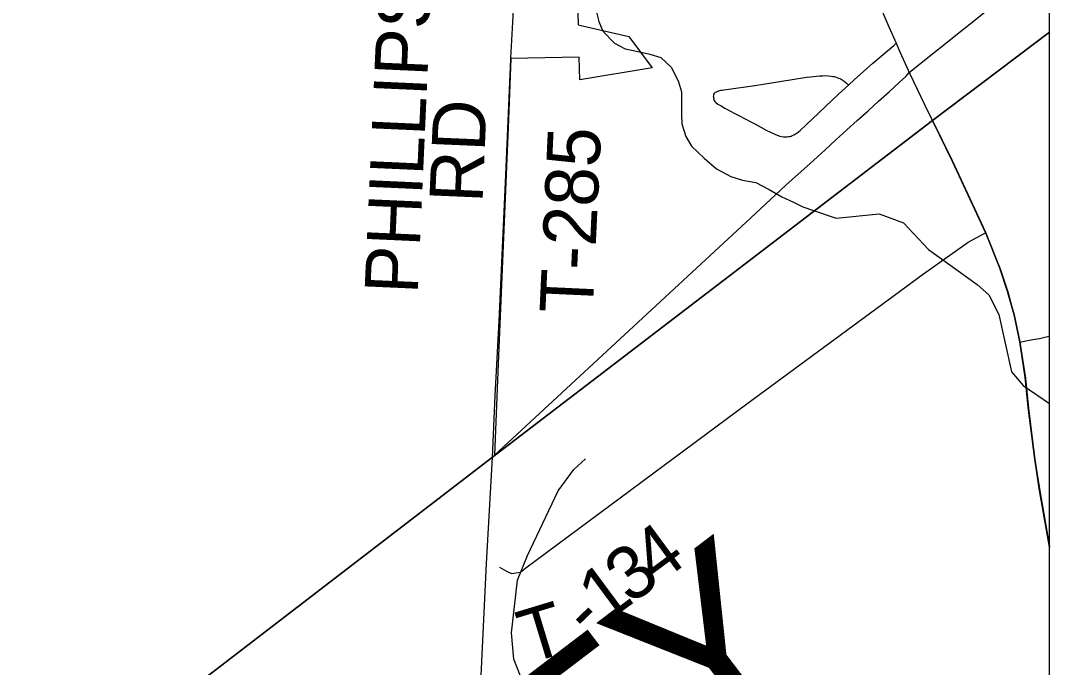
# Model space of a CAD drawing. Extents: x 0 to 1052, y -194 to 246.
# Drawn here: x 7.683 to 8.782, y 19.757 to 20.448 of the extents above; entities that cross this region are included whole.
import ezdxf

# ---------------------------------------------------------------- set-up
doc = ezdxf.new("R2010")
doc.units = 0
for name, color, linetype in [('GM_X_City_Street', 7, 'Continuous'), ('GM_X_Corporation', 7, 'Continuous'), ('GM_X_County_Road', 7, 'Continuous'), ('GM_X_County_Text', 7, 'Continuous'), ('GM_X_Major_River', 7, 'Continuous'), ('GM_X_Minor_River', 7, 'Continuous'), ('GM_X_State_Route', 7, 'Continuous'), ('GM_X_Township_Road', 7, 'Continuous'), ('GM_X_Township_Road_Text', 7, 'Continuous')]:
    doc.layers.add(name, color=color, linetype=linetype)

msp = doc.modelspace()

# ---------------------------------------------------------------- linework, layer by layer
at = {"layer": 'GM_X_City_Street'}
for points in [[(8.4233, 20.3666), (8.4232, 20.3657), (8.4233, 20.3649), (8.4235, 20.364), (8.4238, 20.3629), (8.4241, 20.3623), (8.4248, 20.3613), (8.4259, 20.3601), (8.4281, 20.3584), (8.4315, 20.3564), (8.4356, 20.354), (8.4462, 20.3485), (8.4505, 20.3462), (8.4639, 20.3391), (8.4675, 20.3372), (8.4804, 20.3303), (8.4841, 20.3284), (8.4887, 20.3263), (8.4915, 20.3252), (8.4942, 20.3242), (8.498, 20.3235), (8.5001, 20.3234), (8.5021, 20.3234), (8.5036, 20.3236), (8.5048, 20.3238), (8.5062, 20.3242), (8.5075, 20.3247), (8.509, 20.3254), (8.511, 20.3265), (8.5123, 20.3273), (8.5141, 20.3287), (8.516, 20.3303), (8.5219, 20.336), (8.5568, 20.3688), (8.5678, 20.3789), (8.5737, 20.3843), (8.5936, 20.4021), (8.6158, 20.4211), (8.6185, 20.4234)], [(8.4233, 20.3666), (8.4236, 20.368), (8.4238, 20.3688), (8.4244, 20.3699), (8.4249, 20.3704), (8.4256, 20.371), (8.4264, 20.3715), (8.4273, 20.3719), (8.4281, 20.3722), (8.4291, 20.3726), (8.431, 20.3731), (8.4323, 20.3733), (8.4344, 20.3737), (8.4372, 20.3741), (8.4674, 20.3783), (8.4852, 20.3811), (8.5073, 20.3846), (8.5228, 20.387), (8.5269, 20.3875), (8.5364, 20.3886), (8.54, 20.3887), (8.5426, 20.3888), (8.549, 20.3883), (8.5508, 20.388), (8.5526, 20.3877), (8.5545, 20.3871), (8.5569, 20.3862), (8.5582, 20.3857), (8.5597, 20.3849), (8.5619, 20.3835), (8.563, 20.3827), (8.565, 20.3811), (8.5666, 20.3798), (8.5678, 20.3789)]]:
    msp.add_lwpolyline(points, dxfattribs=at)
at = {"layer": 'GM_X_Corporation'}
for points in [[(5.1788, 17.6981), (5.491, 17.9457), (6.1888, 18.4644), (6.5994, 18.7694), (6.8785, 18.9763), (8.1871, 19.9814), (8.6571, 20.341), (8.7822, 20.435), (8.7822, 21.0055), (1.9822, 21.0055), (1.9822, 14.2055)], [(8.2775, 20.4921), (8.2789, 20.4431), (8.3329, 20.4307), (8.3577, 20.3971), (8.2807, 20.3841), (8.2799, 20.4085), (8.2069, 20.4072), (8.2042, 20.3419), (8.1934, 20.0815), (8.1894, 19.9837), (8.4627, 20.2366), (8.5007, 20.2717), (8.5265, 20.2951), (8.5421, 20.3093), (8.5541, 20.3202), (8.5659, 20.3308), (8.5769, 20.3408), (8.5885, 20.3513), (8.5997, 20.3615), (8.6112, 20.3719), (8.6216, 20.3813), (8.6288, 20.3878), (8.6327, 20.3925), (8.7822, 20.512)], [(8.7822, 14.2055), (8.7822, 20.435), (8.6571, 20.341), (8.1871, 19.9814), (6.8785, 18.9763), (6.5994, 18.7694), (6.1888, 18.4644), (5.491, 17.9457), (5.1788, 17.6981)], [(8.7822, 14.2055), (8.7822, 19.8853), (8.7716, 19.9458), (8.7665, 19.9791), (8.7595, 20.0343), (8.7564, 20.0663), (8.7504, 20.1046), (8.7444, 20.1332), (8.7375, 20.1583), (8.7292, 20.1831), (8.7137, 20.2216), (8.6781, 20.298), (8.6571, 20.341), (8.1871, 19.9814), (6.8785, 18.9763), (6.5994, 18.7694), (6.1888, 18.4644), (5.491, 17.9457), (5.1788, 17.6981)]]:
    msp.add_lwpolyline(points, dxfattribs=at)
for points in [[(8.7822, 20.435), (8.7822, 21.0055), (5.5898, 21.0055), (5.6935, 20.5776), (5.9283, 19.6076), (5.992, 19.3448), (6.152, 18.6129), (6.1888, 18.4644), (6.5994, 18.7694), (6.8785, 18.9763), (8.1871, 19.9814), (8.6571, 20.341)], [(8.7822, 19.8853), (8.7822, 20.435), (8.6571, 20.341), (8.6781, 20.298), (8.7137, 20.2216), (8.7292, 20.1831), (8.7375, 20.1583), (8.7444, 20.1332), (8.7504, 20.1046), (8.7564, 20.0663), (8.7595, 20.0343), (8.7665, 19.9791), (8.7716, 19.9458)]]:
    msp.add_lwpolyline(points, close=True, dxfattribs=at)
at = {"layer": 'GM_X_County_Road'}
msp.add_lwpolyline([(8.7507, 20.1041), (8.7587, 20.1058), (8.7645, 20.107), (8.7715, 20.1082), (8.7771, 20.1095), (8.782, 20.1106), (8.7822, 20.1107)], dxfattribs=at)
at = {"layer": 'GM_X_Major_River'}
msp.add_lwpolyline([(8.298, 20.458), (8.3008, 20.4466), (8.3052, 20.4363), (8.3176, 20.4236), (8.3289, 20.4174), (8.341, 20.415), (8.3553, 20.4118), (8.367, 20.4082), (8.3783, 20.3974), (8.386, 20.3822), (8.3893, 20.3715), (8.389, 20.3468), (8.3896, 20.3373), (8.3936, 20.3236), (8.3999, 20.3133), (8.4134, 20.3006), (8.4265, 20.2891), (8.4419, 20.2809), (8.4544, 20.277), (8.4687, 20.2745), (8.4827, 20.2671), (8.4962, 20.2593), (8.5086, 20.2535), (8.5188, 20.2488), (8.5302, 20.2449)], dxfattribs=at)
at = {"layer": 'GM_X_Minor_River'}
for points in [[(8.298, 20.458), (8.3008, 20.4466), (8.3052, 20.4363), (8.3176, 20.4236), (8.3289, 20.4174), (8.341, 20.415), (8.3553, 20.4118), (8.367, 20.4082), (8.3783, 20.3974), (8.386, 20.3822), (8.3893, 20.3715), (8.389, 20.3468), (8.3896, 20.3373), (8.3936, 20.3236), (8.3999, 20.3133), (8.4134, 20.3006), (8.4265, 20.2891), (8.4419, 20.2809), (8.4544, 20.277), (8.4687, 20.2745), (8.4827, 20.2671), (8.4962, 20.2593), (8.5086, 20.2535), (8.5188, 20.2488), (8.5302, 20.2449)], [(8.5302, 20.2449), (8.5543, 20.2366), (8.6002, 20.2411), (8.6262, 20.2316), (8.653, 20.2032)], [(8.653, 20.2032), (8.7048, 20.1656), (8.7176, 20.1547), (8.7282, 20.1337), (8.7417, 20.0725), (8.754, 20.0579), (8.7822, 20.0388)], [(8.2244, 19.7293), (8.2102, 19.7659), (8.2076, 19.7937), (8.2138, 19.8501), (8.2248, 19.8765), (8.2574, 19.9454), (8.274, 19.9682), (8.2867, 19.9798)]]:
    msp.add_lwpolyline(points, dxfattribs=at)
at = {"layer": 'GM_X_State_Route'}
for points in [[(8.5617, 20.5552), (8.5633, 20.5516), (8.5773, 20.5194), (8.5924, 20.4845), (8.5952, 20.4777), (8.5965, 20.4746), (8.5993, 20.4677), (8.6097, 20.4434), (8.6185, 20.4234), (8.6224, 20.4143), (8.6332, 20.3906)], [(8.6332, 20.3906), (8.6488, 20.3579), (8.6573, 20.3405)], [(8.6573, 20.3405), (8.6783, 20.2975), (8.7139, 20.2211), (8.7294, 20.1826), (8.7378, 20.1578), (8.7446, 20.1327), (8.7507, 20.1041), (8.7567, 20.0657), (8.7597, 20.0338), (8.7667, 19.9786), (8.7718, 19.9453), (8.7822, 19.886)]]:
    msp.add_lwpolyline(points, dxfattribs=at)
at = {"layer": 'GM_X_Township_Road'}
for points in [[(8.2067, 20.4065), (8.2067, 20.4075), (8.2099, 20.465), (8.2104, 20.4731), (8.2109, 20.483), (8.2113, 20.4901), (8.2118, 20.4999), (8.2126, 20.5203), (8.2131, 20.545)], [(8.1873, 19.9809), (8.1902, 20.0468), (8.1945, 20.1268), (8.2013, 20.2746), (8.2067, 20.4065)], [(8.1946, 19.8639), (8.2021, 19.8596), (8.2074, 19.8572), (8.2173, 19.8588), (8.2227, 19.8632), (8.4591, 20.0384), (8.6476, 20.177), (8.6955, 20.211), (8.7139, 20.2211)], [(8.6429, 19.2363), (8.3009, 19.274), (8.1934, 19.2844), (8.176, 19.2868), (8.1769, 19.319), (8.183, 19.4077), (8.1836, 19.4145), (8.1784, 19.4203), (8.1716, 19.422), (8.1664, 19.4256), (8.1609, 19.4318), (8.1609, 19.4485), (8.1807, 19.8678), (8.1873, 19.9809)]]:
    msp.add_lwpolyline(points, dxfattribs=at)

# ---------------------------------------------------------------- texts
at = {"layer": 'GM_X_County_Text'}
msp.add_text('HIGHLAND COUNTY', height=0.189394, rotation=37.2438, dxfattribs=at).set_placement((6.5935, 18.2705))
at = {"layer": 'GM_X_Township_Road_Text'}
for s, height, rotation, p in [('PHILLIPS', 0.05682, 87.4332, (8.1073, 20.155)), ('RD', 0.05682, 87.5314, (8.1765, 20.2523)), ('T-285', 0.05682, 87.366, (8.2942, 20.1341)), ('4', 0.0568, 36.4015, (8.3629, 19.8442)), ('3', 0.0568, 36.4276, (8.3347, 19.8234)), ('1', 0.0568, 36.5389, (8.3066, 19.8026)), ('T', 0.0568, 16.8979, (8.2256, 19.7606)), ('-', 0.0568, 43.9869, (8.2913, 19.7876))]:
    msp.add_text(s, height=height, rotation=rotation, dxfattribs=at).set_placement(p)

doc.saveas('drawing.dxf')
